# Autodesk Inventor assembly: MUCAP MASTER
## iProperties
Shininess: 64.0
Length Units: 11272
Angle Units: 11279
Time Units: 11290
Mass Units: 11286
Length Display Precision: 3
Angle Display Precision: 2
Compacted: True
Part Number: MUCAP MASTER
Document SubType Name: Assembly
Created: 2004-08
Designer: John Blackburn
Manufacturer: Standard
Standards Organization: Custom
Density: 0.0
Volumn: 0.0
Area: 0.0
PropertySet Name: Model Information
Control State: 0
Master: False
Checked Out: False
Author: John Blackburn
